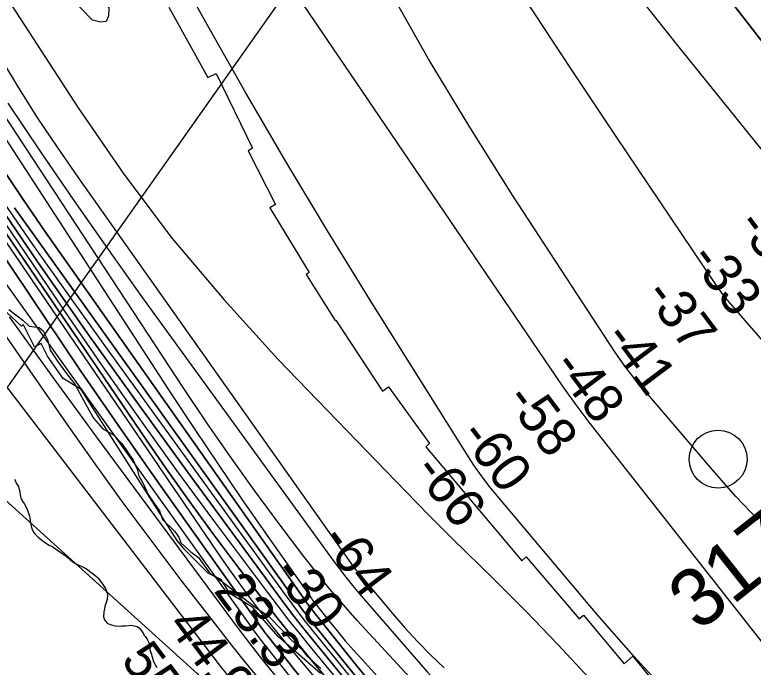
# Model space of a CAD drawing. Extents: x 3172231 to 3210228, y 940198 to 965780.
# Drawn here: x 3189862 to 3191136, y 948476 to 949601 of the extents above; entities that cross this region are included whole.
import ezdxf

# ---------------------------------------------------------------- set-up
doc = ezdxf.new("R2010")
doc.units = 0
for name, color, linetype in [('V-RIVR-EDGE', 7, 'Continuous'), ('V-RIVR-IDEN', 7, 'Continuous'), ('V-RIVR-MILE', 7, 'Continuous'), ('V-RIVR-RANG', 7, 'Continuous'), ('V-RRAP-RVMT', 7, 'Continuous'), ('V-SITE-VEGE', 7, 'Continuous'), ('V-TOPO-DPTH', 7, 'Continuous'), ('V-TOPO-MAJR', 7, 'Continuous'), ('V-TOPO-MINR', 7, 'Continuous'), ('V-TOPO-WATR', 7, 'Continuous')]:
    doc.layers.add(name, color=color, linetype=linetype)

msp = doc.modelspace()

# ---------------------------------------------------------------- linework, layer by layer
at = {"layer": 'V-RIVR-EDGE'}
for points in [[(3189851.765, 949092.962), (3189876.095, 949074.751), (3189886.96, 949064.351), (3189904.07, 949062.234), (3189911.316, 949056.512), (3189918.54, 949041.454), (3189923.162, 949023.29), (3189937.114, 949002.511), (3189953.137, 948980.689), (3189965.544, 948964.581), (3189974.321, 948948.482), (3189986.711, 948925.632), (3189998.072, 948905.896), (3190014.105, 948887.705), (3190032.748, 948876.768), (3190046.715, 948862.212), (3190066.352, 948833.639), (3190073.055, 948818.064), (3190076.139, 948806.646), (3190082.85, 948794.183), (3190092.135, 948773.934), (3190102.988, 948758.348), (3190111.774, 948745.879), (3190116.923, 948730.827), (3190137.619, 948711.068), (3190144.854, 948700.678), (3190148.46, 948690.815), (3190165.536, 948675.214), (3190178.995, 948665.327), (3190198.12, 948639.348), (3190217.793, 948625.297), (3190253.51, 948597.722), (3190282.499, 948575.868), (3190299.068, 948564.936), (3190323.9, 948539.98), (3190338.899, 948523.347), (3190357.009, 948506.707), (3190366.316, 948495.274)], [(3190366.316, 948495.274), (3190390.12, 948473.951)]]:
    msp.add_lwpolyline(points, dxfattribs=at)
at = {"layer": 'V-RIVR-MILE'}
msp.add_circle((3191075.186, 948835.18), 50, dxfattribs=at)
at = {"layer": 'V-RIVR-RANG'}
msp.add_lwpolyline([(3189710.254, 948762.817), (3192054.86, 952083.494)], dxfattribs=at)
at = {"layer": 'V-RRAP-RVMT'}
for p, q in [((3190127.846, 949614.295), (3190194.985, 949493.333)), ((3190194.985, 949493.333), (3190209.726, 949499.871)), ((3190209.726, 949499.871), (3190272.236, 949371.192)), ((3190272.236, 949371.192), (3190264.358, 949366.77)), ((3190264.358, 949366.77), (3190312.067, 949274.315)), ((3190312.067, 949274.315), (3190301.86, 949268.59)), ((3190301.86, 949268.59), (3190369.639, 949156.715)), ((3190369.639, 949156.715), (3190364.496, 949153.411)), ((3190364.496, 949153.411), (3190414.678, 949073.924)), ((3189873.482, 949064.26), (3189799.138, 949133.182)), ((3190414.678, 949073.924), (3190415.815, 949074.665)), ((3190415.815, 949074.665), (3190496.44, 948952.37)), ((3189877.134, 949066.69), (3189873.482, 949064.26)), ((3189896.254, 949028.729), (3189877.134, 949066.69)), ((3189907.844, 949034.612), (3189896.254, 949028.729)), ((3189918.584, 949012.854), (3189907.844, 949034.612)), ((3189945.351, 948974.252), (3189918.584, 949012.854)), ((3189976.69, 948955.466), (3189945.351, 948974.252)), ((3190142.239, 948695.047), (3189976.69, 948955.466)), ((3190496.44, 948952.37), (3190506.919, 948959.739)), ((3190506.919, 948959.739), (3190577.611, 948862.06)), ((3190577.611, 948862.06), (3190570.818, 948856.141)), ((3190570.818, 948856.141), (3190736.934, 948660)), ((3190155.247, 948678.671), (3190142.239, 948695.047)), ((3190195.479, 948638.769), (3190155.247, 948678.671)), ((3190736.934, 948660), (3190744.329, 948666.494)), ((3190744.329, 948666.494), (3190835.507, 948560.053)), ((3190217.863, 948627.901), (3190195.479, 948638.769)), ((3190233.111, 948603.756), (3190217.863, 948627.901)), ((3190272.399, 948579.432), (3190233.111, 948603.756)), ((3190316.177, 948529.551), (3190272.399, 948579.432)), ((3190835.507, 948560.053), (3190843.017, 948566.427)), ((3190843.017, 948566.427), (3190913.135, 948482.491)), ((3190389.336, 948465.465), (3190316.177, 948529.551)), ((3190913.135, 948482.491), (3190928.391, 948495.235)), ((3190928.391, 948495.235), (3191010.045, 948395.015))]:
    msp.add_line(p, q, dxfattribs=at)
at = {"layer": 'V-SITE-VEGE'}
for p, q in [((3189861.336, 948799.926), (3189863.101, 948796.95)), ((3189863.101, 948796.95), (3189864.498, 948793.98)), ((3189864.498, 948793.98), (3189868.395, 948788.019)), ((3189868.395, 948788.019), (3189869.059, 948785.069)), ((3189869.059, 948785.069), (3189870.083, 948781.743)), ((3189870.083, 948781.743), (3189872.014, 948770.324)), ((3189872.014, 948770.324), (3189872.688, 948767.739)), ((3189872.688, 948767.739), (3189875.85, 948761.798)), ((3189875.85, 948761.798), (3189877.98, 948758.81)), ((3189877.98, 948758.81), (3189882.201, 948751.005)), ((3189882.201, 948751.005), (3189884.638, 948745.445)), ((3189884.638, 948745.445), (3189886.019, 948741.744)), ((3189886.019, 948741.744), (3189887.364, 948736.577)), ((3189887.364, 948736.577), (3189888.021, 948733.257)), ((3189888.021, 948733.257), (3189888.658, 948729.208)), ((3189888.658, 948729.208), (3189888.941, 948725.532)), ((3189888.941, 948725.532), (3189891.632, 948715.196)), ((3189891.632, 948715.196), (3189895.153, 948708.876)), ((3189895.153, 948708.876), (3189897.285, 948705.892)), ((3189897.285, 948705.892), (3189902.296, 948700.637)), ((3189902.296, 948700.637), (3189911.657, 948693.079)), ((3189911.657, 948693.079), (3189921.42, 948686.978)), ((3189921.42, 948686.978), (3189925.412, 948685.051)), ((3189925.412, 948685.051), (3189927.951, 948683.89)), ((3189927.951, 948683.89), (3189929.752, 948682.381)), ((3189929.752, 948682.381), (3189935.889, 948678.201)), ((3189935.889, 948678.201), (3189943.469, 948672.886)), ((3189943.469, 948672.886), (3189947.076, 948670.234)), ((3189947.076, 948670.234), (3189950.692, 948667.946)), ((3189950.692, 948667.946), (3189955.005, 948664.176)), ((3189955.005, 948664.176), (3189957.512, 948661.55)), ((3189957.512, 948661.55), (3189960.037, 948659.656)), ((3189960.037, 948659.656), (3189967.992, 948654.7)), ((3189967.992, 948654.7), (3189972.34, 948652.396)), ((3189972.34, 948652.396), (3189980.329, 948648.906)), ((3189980.329, 948648.906), (3189982.504, 948647.753)), ((3189982.504, 948647.753), (3189985.76, 948645.842)), ((3189985.76, 948645.842), (3189998.022, 948636.749)), ((3189998.022, 948636.749), (3190003.06, 948632.596)), ((3190003.06, 948632.596), (3190005.208, 948630.343)), ((3190005.208, 948630.343), (3190008.065, 948626.974)), ((3190008.065, 948626.974), (3190012.683, 948620.629)), ((3190012.683, 948620.629), (3190018.352, 948612.056)), ((3190018.352, 948612.056), (3190020.441, 948607.24)), ((3190020.441, 948607.24), (3190021.471, 948604.278)), ((3190022.129, 948600.962), (3190021.205, 948592.912)), ((3190021.471, 948604.278), (3190022.129, 948600.962)), ((3190021.205, 948592.912), (3190017.621, 948580.89)), ((3190015.573, 948571.764), (3190015.374, 948563.33)), ((3190016.794, 948576.874), (3190015.573, 948571.764)), ((3190017.621, 948580.89), (3190016.794, 948576.874)), ((3190015.374, 948563.33), (3190016.72, 948558.163)), ((3190016.72, 948558.163), (3190021.356, 948552.552)), ((3190021.356, 948552.552), (3190026.44, 948550.229)), ((3190026.44, 948550.229), (3190035.189, 948547.823)), ((3190035.189, 948547.823), (3190041.779, 948547.301)), ((3190041.779, 948547.301), (3190046.555, 948547.557)), ((3190046.555, 948547.557), (3190049.496, 948547.854)), ((3190049.496, 948547.854), (3190052.797, 948547.776)), ((3190052.797, 948547.776), (3190062.724, 948548.642)), ((3190062.724, 948548.642), (3190065.649, 948548.208)), ((3190065.649, 948548.208), (3190070.39, 948546.996)), ((3190070.39, 948546.996), (3190073.314, 948546.559)), ((3190073.314, 948546.559), (3190077.287, 948543.897)), ((3190077.287, 948543.897), (3190080.843, 948539.045)), ((3190080.843, 948539.045), (3190084.023, 948533.833)), ((3190084.023, 948533.833), (3190085.428, 948531.232)), ((3190085.428, 948531.232), (3190086.854, 948529.364)), ((3190086.854, 948529.364), (3190088.285, 948527.863)), ((3190088.285, 948527.863), (3190090.415, 948524.879)), ((3190090.415, 948524.879), (3190093.221, 948519.309)), ((3190093.221, 948519.309), (3190094.874, 948511.565)), ((3190094.874, 948511.565), (3190095.136, 948507.158)), ((3190095.136, 948507.158), (3190097.163, 948499.773)), ((3190097.163, 948499.773), (3190099.236, 948494.221)), ((3190099.236, 948494.221), (3190101.622, 948486.459)), ((3190101.622, 948486.459), (3190104.765, 948479.78)), ((3190104.765, 948479.78), (3190106.871, 948475.696))]:
    msp.add_line(p, q, dxfattribs=at)
at = {"layer": 'V-TOPO-DPTH'}
for points in [[(3192012.955, 948602.614), (3191930.959, 948687.595), (3191873.611, 948747.209), (3191816.383, 948806.938), (3191759.336, 948866.84), (3191702.409, 948926.855), (3191394.184, 949252.785), (3191387.477, 949259.877), (3191380.77, 949266.97), (3191374.064, 949274.062), (3191367.357, 949281.155), (3191360.976, 949287.904), (3191357.496, 949291.654), (3191354.065, 949295.447), (3191350.705, 949299.304), (3191347.394, 949303.204), (3191341.968, 949309.719), (3191341.41, 949310.397), (3191339.768, 949312.455), (3190909.362, 949866.816)], [(3190909.362, 949866.816), (3191339.768, 949312.455), (3191341.41, 949310.397), (3191341.968, 949309.719), (3191347.394, 949303.204), (3191350.705, 949299.304), (3191354.065, 949295.447), (3191357.496, 949291.654), (3191360.976, 949287.904), (3191367.357, 949281.155), (3191374.064, 949274.062), (3191380.77, 949266.97), (3191387.477, 949259.877), (3191394.184, 949252.785), (3191702.409, 948926.855), (3191759.336, 948866.84), (3191816.383, 948806.938), (3191873.611, 948747.209), (3191930.959, 948687.595), (3192012.955, 948602.614)], [(3191986.372, 948408.73), (3191976.784, 948416.825), (3191967.343, 948425.085), (3191958.124, 948433.592), (3191949.053, 948442.263), (3191928.208, 948462.722), (3191926.071, 948464.871), (3191923.97, 948467.053), (3191921.923, 948469.286), (3191919.911, 948471.552), (3191382.578, 949091.833), (3191360.655, 949117.164), (3191338.748, 949142.51), (3191316.866, 949167.878), (3191295.001, 949193.259), (3191260.173, 949233.726), (3191255.758, 949238.905), (3191251.377, 949244.112), (3191247.046, 949249.361), (3191242.748, 949254.637), (3191005.862, 949548.332), (3190925.504, 949649.973)], [(3191986.372, 948408.73), (3191976.784, 948416.825), (3191967.343, 948425.085), (3191958.124, 948433.592), (3191949.053, 948442.263), (3191928.208, 948462.722), (3191926.071, 948464.871), (3191923.97, 948467.053), (3191921.923, 948469.286), (3191919.911, 948471.552), (3191382.578, 949091.833), (3191360.655, 949117.164), (3191338.748, 949142.51), (3191316.866, 949167.878), (3191295.001, 949193.259), (3191260.173, 949233.726), (3191255.758, 949238.905), (3191251.377, 949244.112), (3191247.046, 949249.361), (3191242.748, 949254.637), (3191005.862, 949548.332), (3190925.504, 949649.973)], [(3189736.246, 949555.636), (3190132.964, 948946.329), (3190172.592, 948886.17), (3190212.646, 948826.299), (3190253.338, 948766.86), (3190294.455, 948707.708), (3190374.271, 948594.182), (3190375.818, 948592.024), (3190377.391, 948589.884), (3190379.002, 948587.773), (3190380.639, 948585.682), (3190404.493, 948555.76), (3190418.241, 948538.863), (3190432.211, 948522.155), (3190446.511, 948505.729), (3190461.032, 948489.491), (3190507.779, 948438.256)], [(3189736.246, 949555.636), (3190132.964, 948946.329), (3190172.592, 948886.17), (3190212.646, 948826.299), (3190253.338, 948766.86), (3190294.455, 948707.708), (3190374.271, 948594.182), (3190375.818, 948592.024), (3190377.391, 948589.884), (3190379.002, 948587.773), (3190380.639, 948585.682), (3190404.493, 948555.76), (3190418.241, 948538.863), (3190432.211, 948522.155), (3190446.511, 948505.729), (3190461.032, 948489.491), (3190507.779, 948438.256)], [(3190956.043, 947800.747), (3190919.634, 947840.373), (3190883.674, 947880.397), (3190848.389, 947921.017), (3190813.553, 947962.034), (3190369.937, 948493.322), (3190346.753, 948521.468), (3190323.822, 948549.816), (3190301.271, 948578.467), (3190278.973, 948607.32), (3190243.332, 948654.081), (3190203.836, 948706.778), (3190164.916, 948759.889), (3190126.858, 948813.622), (3190089.376, 948867.77), (3189655.811, 949505.052)], [(3189655.811, 949505.052), (3190089.376, 948867.77), (3190126.858, 948813.622), (3190164.916, 948759.889), (3190203.836, 948706.778), (3190243.332, 948654.081), (3190278.973, 948607.32), (3190301.271, 948578.467), (3190323.822, 948549.816), (3190346.753, 948521.468), (3190369.937, 948493.322), (3190813.553, 947962.034), (3190848.389, 947921.017), (3190883.674, 947880.397), (3190919.634, 947840.373), (3190956.043, 947800.747)], [(3191003.798, 947703.104), (3190371.389, 948440.144), (3190358.843, 948454.937), (3190346.412, 948469.826), (3190334.153, 948484.856), (3190322.008, 948499.982), (3190300.709, 948526.825), (3190297.937, 948530.408), (3190296.588, 948532.227), (3190295.256, 948534.06), (3190168.365, 948711.421), (3190104.034, 948802.244), (3190040.277, 948893.464), (3189977.384, 948985.282), (3189915.067, 949077.497), (3189649.664, 949474.253)], [(3189835.656, 949342.933), (3189875.193, 949284.61), (3189915.335, 949226.69), (3190359.307, 948596.551), (3190364.024, 948589.98), (3190368.818, 948583.467), (3190373.727, 948577.041), (3190378.713, 948570.671), (3190451.359, 948479.548), (3190493.222, 948428.084), (3190535.747, 948377.184), (3190579.265, 948327.131), (3190623.446, 948277.642), (3190987.871, 947877.426), (3190999.332, 947864.938), (3191010.859, 947852.511), (3191022.483, 947840.176), (3191034.173, 947827.902), (3191041.949, 947819.8)], [(3191041.949, 947819.8), (3191034.173, 947827.902), (3191022.483, 947840.176), (3191010.859, 947852.511), (3190999.332, 947864.938), (3190987.871, 947877.426), (3190623.446, 948277.642), (3190579.265, 948327.131), (3190535.747, 948377.184), (3190493.222, 948428.084), (3190451.359, 948479.548), (3190378.713, 948570.671), (3190373.727, 948577.041), (3190368.818, 948583.467), (3190364.024, 948589.98), (3190359.307, 948596.551), (3189915.335, 949226.69), (3189875.193, 949284.61), (3189835.656, 949342.933)], [(3191023.364, 947770.724), (3190904.893, 947898.407), (3190832.346, 947978.08), (3190760.814, 948058.638), (3190690.804, 948140.522), (3190621.809, 948223.289), (3190373.515, 948526.887), (3190358.418, 948545.638), (3190343.515, 948564.539), (3190328.902, 948583.666), (3190314.483, 948602.943), (3190164.377, 948806.86), (3190075.773, 948928.719), (3189988.133, 949051.259), (3189901.938, 949174.82), (3189816.707, 949299.062)], [(3189816.707, 949299.062), (3189901.938, 949174.82), (3189988.133, 949051.259), (3190075.773, 948928.719), (3190164.377, 948806.86), (3190314.483, 948602.943), (3190328.902, 948583.666), (3190343.515, 948564.539), (3190358.418, 948545.638), (3190373.515, 948526.887), (3190621.809, 948223.289), (3190690.804, 948140.522), (3190760.814, 948058.638), (3190832.346, 947978.08), (3190904.893, 947898.407), (3191023.364, 947770.724)], [(3189861.87, 949268.627), (3190340.799, 948599.332), (3190349.481, 948587.412), (3190358.294, 948575.592), (3190367.304, 948563.922), (3190376.446, 948552.352), (3190500.175, 948398.426), (3190572.135, 948310.703), (3190645.234, 948223.96), (3190720.042, 948138.686), (3190795.989, 948054.391), (3191058.755, 947768.507)], [(3191058.755, 947768.507), (3190795.989, 948054.391), (3190720.042, 948138.686), (3190645.234, 948223.96), (3190572.135, 948310.703), (3190500.175, 948398.426), (3190376.446, 948552.352), (3190367.304, 948563.922), (3190358.294, 948575.592), (3190349.481, 948587.412), (3190340.799, 948599.332), (3189861.87, 949268.627)]]:
    msp.add_lwpolyline(points, dxfattribs=at)
at = {"layer": 'V-TOPO-MAJR'}
for points in [[(3190743.211, 949626.402), (3190820.749, 949508.682), (3190898.951, 949391.396), (3191069.546, 949137.865), (3191076.408, 949128.07), (3191083.506, 949118.456), (3191090.959, 949109.114), (3191098.649, 949099.954), (3191170.131, 949017.974)], [(3191154.681, 947871.381), (3191126.651, 947893.029), (3191126.118, 947893.444), (3191098.181, 947915.734), (3191070.624, 947938.473), (3191043.637, 947961.886), (3191017.03, 947985.747), (3190920.418, 948074.564), (3190846.679, 948144.062), (3190774.125, 948214.745), (3190703.348, 948287.208), (3190633.756, 948360.857), (3190452.822, 948557.164), (3190428.905, 948583.887), (3190405.525, 948611.058), (3190382.949, 948638.901), (3190360.91, 948667.193), (3190318.117, 948723.816), (3190275.654, 948781.158), (3190233.951, 948839.037), (3190193.388, 948897.719), (3190153.584, 948956.938), (3189741.723, 949582.816)], [(3189572.544, 949441.368), (3189951.891, 948895.282), (3189999.909, 948827.269), (3190048.609, 948759.756), (3190098.331, 948692.992), (3190148.735, 948626.727), (3190211.647, 948545.313), (3190231.262, 948520.256), (3190251.084, 948495.367), (3190271.218, 948470.73), (3190291.559, 948446.259), (3190602.355, 948077.126), (3190661.339, 948007.74), (3190720.757, 947938.732), (3190780.826, 947870.291), (3190841.33, 947802.226)]]:
    msp.add_lwpolyline(points, dxfattribs=at)
at = {"layer": 'V-TOPO-MINR'}
for points in [[(3189291.749, 950764.668), (3189922.693, 949778.714), (3189930.109, 949767.043), (3189937.476, 949755.341), (3189944.768, 949743.592), (3189952.01, 949731.811), (3190024.204, 949613.539), (3190023.969, 949599.209), (3190019.826, 949589.958), (3190009.822, 949588.329), (3189995.911, 949591.779), (3189916.969, 949674.31), (3189897.166, 949693.847), (3189876.664, 949712.573), (3189855.114, 949730.082)], [(3191172.379, 948492.47), (3190854.559, 948896.762), (3190842.281, 948912.719), (3190830.228, 948928.841), (3190818.512, 948945.21), (3190807.022, 948961.744), (3190176.694, 949889.17)], [(3192012.955, 948602.614), (3191930.959, 948687.595), (3191873.611, 948747.209), (3191816.383, 948806.938), (3191759.336, 948866.84), (3191702.409, 948926.855), (3191394.184, 949252.785), (3191387.477, 949259.877), (3191380.77, 949266.97), (3191374.064, 949274.062), (3191367.357, 949281.155), (3191360.976, 949287.904), (3191357.496, 949291.654), (3191354.065, 949295.447), (3191350.705, 949299.304), (3191347.394, 949303.204), (3191341.968, 949309.719), (3191341.41, 949310.397), (3191339.768, 949312.455), (3190909.362, 949866.816)], [(3191241.524, 948190.066), (3191131.775, 948290.836), (3191062.425, 948356.998), (3190994.832, 948424.845), (3190929.877, 948495.222), (3190866.681, 948567.285), (3190694.76, 948771.046), (3190680.563, 948788.612), (3190666.877, 948806.551), (3190653.959, 948825.05), (3190641.553, 948843.923), (3190474.889, 949109.494), (3190401.466, 949228.592), (3190329.326, 949348.447), (3190259.109, 949469.439), (3190190.175, 949591.189), (3190069.133, 949809.008)], [(3189828.143, 949660.88), (3189971.35, 949440.608), (3190050.38, 949326.398), (3190133.575, 949215.505), (3190223.019, 949109.588), (3190316.628, 949006.987), (3190536.413, 948779.622), (3190556.317, 948759.184), (3190576.321, 948738.845), (3190596.476, 948718.656), (3190616.732, 948698.566), (3190688.372, 948628.036), (3190743.943, 948572.205), (3190798.743, 948515.642), (3190852.385, 948457.98), (3190905.255, 948399.586), (3191294.96, 947960.294)], [(3191144.258, 948730.283), (3191105.924, 948770.82), (3191068.767, 948812.52), (3190936.917, 948967.292), (3190926.396, 948980.129), (3190916.211, 948993.218), (3190906.532, 949006.684), (3190897.189, 949020.402), (3190720.812, 949290.265), (3190646.772, 949407.41), (3190575.162, 949525.972), (3190507.198, 949646.662)], [(3191986.372, 948408.73), (3191976.784, 948416.825), (3191967.343, 948425.085), (3191958.124, 948433.592), (3191949.053, 948442.263), (3191928.208, 948462.722), (3191926.071, 948464.871), (3191923.97, 948467.053), (3191921.923, 948469.286), (3191919.911, 948471.552), (3191382.578, 949091.833), (3191360.655, 949117.164), (3191338.748, 949142.51), (3191316.866, 949167.878), (3191295.001, 949193.259), (3191260.173, 949233.726), (3191255.758, 949238.905), (3191251.377, 949244.112), (3191247.046, 949249.361), (3191242.748, 949254.637), (3191005.862, 949548.332), (3190925.504, 949649.973)], [(3189736.246, 949555.636), (3190132.964, 948946.329), (3190172.592, 948886.17), (3190212.646, 948826.299), (3190253.338, 948766.86), (3190294.455, 948707.708), (3190374.271, 948594.182), (3190375.818, 948592.024), (3190377.391, 948589.884), (3190379.002, 948587.773), (3190380.639, 948585.682), (3190404.493, 948555.76), (3190418.241, 948538.863), (3190432.211, 948522.155), (3190446.511, 948505.729), (3190461.032, 948489.491), (3190507.779, 948438.256)], [(3189833.828, 949531.592), (3189866.632, 949478.051), (3189900.259, 949425.045), (3189935.12, 949372.843), (3189970.804, 949321.177), (3190441.802, 948656.061), (3190446.032, 948650.245), (3190450.357, 948644.501), (3190454.825, 948638.869), (3190459.389, 948633.31), (3190513.928, 948568.549), (3190535.088, 948544.336), (3190556.814, 948520.663), (3190579.392, 948497.8), (3190602.536, 948475.476)], [(3189658.098, 949517.424), (3189955.56, 949079.272), (3190016.527, 948990.791), (3190078.298, 948902.883), (3190141.276, 948815.836), (3190205.059, 948729.363), (3190298.1, 948605.031), (3190316.135, 948581.287), (3190334.395, 948557.721), (3190352.993, 948534.419), (3190371.815, 948511.294), (3190715.668, 948094.983), (3190767.997, 948032.766), (3190821.055, 947971.186), (3190875.203, 947910.564), (3190930.078, 947850.58), (3191003.325, 947771.936)], [(3189653.537, 949492.693), (3190218.667, 948663.708), (3190233.348, 948642.604), (3190248.29, 948621.691), (3190263.623, 948601.063), (3190279.219, 948580.626), (3190295.131, 948560.43), (3190311.205, 948540.365), (3190327.521, 948520.496), (3190343.998, 948500.758), (3190915.826, 947824.144)], [(3189649.664, 949474.253), (3189915.067, 949077.497), (3189977.384, 948985.282), (3190040.277, 948893.464), (3190104.034, 948802.244), (3190168.365, 948711.421), (3190295.256, 948534.06), (3190296.588, 948532.227), (3190297.937, 948530.408), (3190300.709, 948526.825), (3190322.008, 948499.982), (3190334.153, 948484.856), (3190346.412, 948469.826), (3190358.843, 948454.937), (3190371.389, 948440.144), (3191003.798, 947703.104)], [(3189850.17, 949448.95), (3189906.574, 949364.75), (3189963.712, 949281.058), (3190021.95, 949198.129), (3190080.922, 949115.708), (3190411.126, 948660.591), (3190422.001, 948646.01), (3190433.125, 948631.627), (3190444.625, 948617.543), (3190456.374, 948603.656), (3190573.673, 948468.665), (3190619.269, 948417.877), (3190665.923, 948368.113), (3190714.164, 948319.886), (3190763.463, 948272.683), (3190813.859, 948226.591), (3190864.659, 948180.954), (3190916.063, 948136), (3190967.87, 948091.5), (3191199.717, 947895.029)], [(3189654.756, 949405.366), (3190276.246, 948537.001), (3190281.623, 948529.611), (3190287.075, 948522.279), (3190292.642, 948515.033), (3190298.284, 948507.844), (3190380.452, 948404.824), (3190427.618, 948346.486), (3190475.293, 948288.575), (3190523.733, 948231.301), (3190572.682, 948174.452), (3190982.548, 947704.784), (3190988.103, 947698.499), (3190993.711, 947692.263), (3190999.397, 947686.099), (3191005.137, 947679.982), (3191821.886, 947045.773), (3191936.602, 946961.604), (3191956.768, 946945.504), (3191975.964, 946928.401), (3191993.708, 946909.795), (3192010.483, 946890.186), (3192012.814, 946887.224)], [(3189835.656, 949342.933), (3189875.193, 949284.61), (3189915.335, 949226.69), (3190359.307, 948596.551), (3190364.024, 948589.98), (3190368.818, 948583.467), (3190373.727, 948577.041), (3190378.713, 948570.671), (3190451.359, 948479.548), (3190493.222, 948428.084), (3190535.747, 948377.184), (3190579.265, 948327.131), (3190623.446, 948277.642), (3190987.871, 947877.426), (3190999.332, 947864.938), (3191010.859, 947852.511), (3191022.483, 947840.176), (3191034.173, 947827.902), (3191041.949, 947819.8)], [(3189816.707, 949299.062), (3189901.938, 949174.82), (3189988.133, 949051.259), (3190075.773, 948928.719), (3190164.377, 948806.86), (3190314.483, 948602.943), (3190328.902, 948583.666), (3190343.515, 948564.539), (3190358.418, 948545.638), (3190373.515, 948526.887), (3190621.809, 948223.289), (3190690.804, 948140.522), (3190760.814, 948058.638), (3190832.346, 947978.08), (3190904.893, 947898.407), (3191023.364, 947770.724)], [(3189271.701, 949283.317), (3190177.18, 948464.824), (3190189.741, 948449.425), (3190202.355, 948434.07), (3190215.004, 948418.744), (3190349.973, 948255.782), (3190430.715, 948159.499), (3190512.233, 948063.886), (3190594.915, 947969.277), (3190678.373, 947875.339), (3190859.895, 947673.523), (3190883.501, 947646.818), (3190906.794, 947619.848), (3190929.619, 947592.48), (3190952.131, 947564.847), (3191055.723, 947435.429)], [(3189831.843, 949292.906), (3189892.729, 949205.034), (3189954.486, 949117.772), (3190016.823, 949030.916), (3190328.594, 948601.048), (3190339.925, 948585.686), (3190351.418, 948570.45), (3190363.155, 948555.4), (3190375.055, 948540.474), (3190531.459, 948347.503), (3190616.398, 948244.76), (3190702.639, 948143.146), (3190790.836, 948043.224), (3190880.337, 947944.43), (3191041.855, 947769.581)], [(3189861.87, 949268.627), (3190340.799, 948599.332), (3190349.481, 948587.412), (3190358.294, 948575.592), (3190367.304, 948563.922), (3190376.446, 948552.352), (3190500.175, 948398.426), (3190572.135, 948310.703), (3190645.234, 948223.96), (3190720.042, 948138.686), (3190795.989, 948054.391), (3191058.755, 947768.507)], [(3189726.179, 949118.6), (3190220.44, 948473.312), (3190220.888, 948472.734), (3190221.342, 948472.162), (3190224.465, 948468.273), (3190226.272, 948466.057), (3190228.1, 948463.86), (3190229.961, 948461.69), (3190231.843, 948459.538), (3190243.425, 948446.5), (3190251.107, 948437.837), (3190258.778, 948429.164), (3190266.435, 948420.478), (3190274.081, 948411.783), (3190785.394, 947829.287), (3190811.718, 947799.441), (3190838.135, 947769.678), (3190864.693, 947740.041), (3190891.344, 947710.487), (3190918.132, 947681.057), (3190945.008, 947651.708), (3190972.017, 947622.481), (3190999.115, 947593.336), (3191258.344, 947315.778)], [(3189852.346, 949080.564), (3189926.591, 948977.784), (3190001.525, 948875.495), (3190249.344, 948540.735), (3190260.572, 948525.792), (3190271.939, 948510.958), (3190283.517, 948496.288), (3190295.235, 948481.726), (3190435.024, 948310.519), (3190517.334, 948210.94), (3190600.435, 948112.032), (3190684.72, 948014.132), (3190769.795, 947916.905), (3190955.962, 947706.712)]]:
    msp.add_lwpolyline(points, dxfattribs=at)
at = {"layer": 'V-TOPO-WATR'}
msp.add_lwpolyline([(3189655.811, 949505.052), (3190089.376, 948867.77), (3190126.858, 948813.622), (3190164.916, 948759.889), (3190203.836, 948706.778), (3190243.332, 948654.081), (3190278.973, 948607.32), (3190301.271, 948578.467), (3190323.822, 948549.816), (3190346.753, 948521.468), (3190369.937, 948493.322), (3190813.553, 947962.034), (3190848.389, 947921.017), (3190883.674, 947880.397), (3190919.634, 947840.373), (3190956.043, 947800.747)], dxfattribs=at)

# ---------------------------------------------------------------- texts
at = {"layer": 'V-RIVR-IDEN'}
msp.add_text('317', height=99.9998, rotation=38.371531, dxfattribs=at).set_placement((3191041.623, 948536.267))
at = {"layer": 'V-RIVR-RANG'}
for s, rotation, p in [('-30', 306.920833, (3191105.6, 949238.366)), ('-33', 306.920833, (3191024.119, 949180.337)), ('-37', 306.920833, (3190945.964, 949117.882)), ('-41', 306.920833, (3190876.525, 949043.827)), ('-48', 306.920833, (3190787.754, 948995.499)), ('-58', 306.920833, (3190706.431, 948937.261)), ('-60', 306.920833, (3190627.484, 948875.859)), ('-66', 306.920833, (3190547.903, 948815.302)), ('-64', 306.920833, (3190387.951, 948695.24)), ('-30', 306.920833, (3190305.043, 948639.11)), ('23.3', 306.678326, (3190203.754, 948608.278)), ('44.9', 306.678326, (3190123.541, 948548.564)), ('55.4', 306.678326, (3190043.642, 948488.427))]:
    msp.add_text(s, height=67, rotation=rotation, dxfattribs=at).set_placement(p)

doc.saveas('drawing.dxf')
